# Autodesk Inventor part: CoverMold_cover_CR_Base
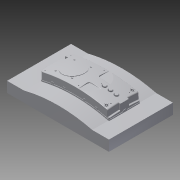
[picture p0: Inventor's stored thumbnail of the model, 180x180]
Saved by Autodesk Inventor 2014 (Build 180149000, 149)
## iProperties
Created: 2009-12
Part Number: CoverMold_cover_CR_Base
Document SubType Name: Modeling
Designer: gaom
Density: 1 g/cm^3
Material: Generic
Appearance: Default
Author: gaom
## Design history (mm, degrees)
node "CoverMold_cover_MP"
sketch "Sketch1"
  geometry: 1 further point
hole "Hole1" sketch "Sketch1" at (70.968, -78) diameter "d0" = 3; stored, may be unused: countersink angle "d4" = 90 deg, drill point angle "d6" = 0 deg; dims "d1" = 6, "d2" = 4, "d3" = 2, "d5" = 8
sketch "Sketch2"
  geometry: 1 further point
hole "Hole2" sketch "Sketch2" at (169.968, -66) diameter "d7" = 3; stored, may be unused: countersink angle "d11" = 90 deg, drill point angle "d13" = 0 deg; dims "d8" = 6, "d9" = 4, "d10" = 2, "d12" = 8
sketch "Sketch3"
  geometry: 1 further point
hole "Hole3" sketch "Sketch3" at (70.968, -142) diameter "d14" = 3; stored, may be unused: countersink angle "d18" = 90 deg, drill point angle "d20" = 0 deg; dims "d15" = 6, "d16" = 4, "d17" = 2, "d19" = 8
sketch "Sketch4"
  geometry: 1 further point
hole "Hole4" sketch "Sketch4" at (169.968, -154) diameter "d21" = 3; stored, may be unused: countersink angle "d25" = 90 deg, drill point angle "d27" = 0 deg; dims "d22" = 6, "d23" = 4, "d24" = 2, "d26" = 8
sketch "Sketch5"
  geometry: 1 further point
hole "Hole5" sketch "Sketch5" at (284.968, -66) diameter "d28" = 3; stored, may be unused: countersink angle "d32" = 90 deg, drill point angle "d34" = 0 deg; dims "d29" = 6, "d30" = 4, "d31" = 2, "d33" = 8
sketch "Sketch6"
  geometry: 1 further point
hole "Hole6" sketch "Sketch6" at (284.968, -154) diameter "d35" = 3; stored, may be unused: countersink angle "d39" = 90 deg, drill point angle "d41" = 0 deg; dims "d36" = 6, "d37" = 4, "d38" = 2, "d40" = 8
feature "Sculpt4"
feature "Solid3::CoverMold_cover_MP"
tag "TaggingFeature1"
body "Solid1"
feature "Surface4"
body "Srf4"
